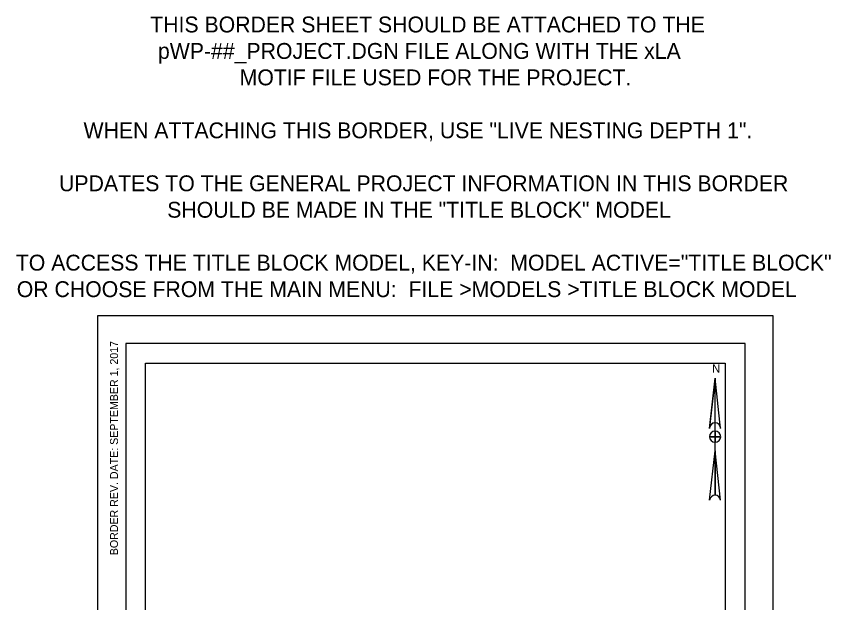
# Model space of a CAD drawing. Extents: x -1 to 9.2, y 0 to 14.8.
# Drawn here: x -1.03 to 9.23, y 7.38 to 14.77 of the extents above; entities that cross this region are included whole.
import ezdxf

# ---------------------------------------------------------------- set-up
doc = ezdxf.new("R2010")
doc.units = 0
for name, color, linetype in [('G-ANNO-SYMB', 7, 'Continuous'), ('G-BORD-LINE', 7, 'Continuous'), ('G-USER-CLIP', 7, 'Continuous'), ('G-USER-PAGE', 7, 'Continuous'), ('G-USER-TEXT', 7, 'Continuous')]:
    doc.layers.add(name, color=color, linetype=linetype)

msp = doc.modelspace()

# ---------------------------------------------------------------- linework, layer by layer
at = {"layer": 'G-ANNO-SYMB'}
for p, q in [((7.702, 9.58), (7.772, 10.213)), ((7.772, 8.738), (7.772, 10.213)), ((7.842, 9.58), (7.772, 10.213)), ((7.772, 9.475), (7.772, 9.546)), ((7.702, 9.475), (7.772, 9.475)), ((7.702, 9.475), (7.702, 9.475)), ((7.702, 9.475), (7.702, 9.475)), ((7.842, 9.475), (7.772, 9.475)), ((7.772, 9.475), (7.772, 9.405)), ((7.842, 9.475), (7.842, 9.475)), ((7.842, 9.475), (7.842, 9.475)), ((7.702, 8.676), (7.772, 9.299)), ((7.841, 8.676), (7.772, 9.299))]:
    msp.add_line(p, q, dxfattribs=at)
for points in [[(7.772, 9.65), (7.772, 9.65), (7.772, 10.213), (7.703, 9.596)], [(7.772, 9.546), (7.772, 9.475), (7.842, 9.475)], [(7.772, 9.405), (7.772, 9.475), (7.702, 9.475), (7.702, 9.475)], [(7.772, 9.405), (7.772, 9.405)], [(7.841, 8.676), (7.772, 9.299), (7.772, 8.738)]]:
    msp.add_lwpolyline(points, dxfattribs=at)
for centre, radius, start, end in [((7.772, 9.58), 0.0703, 90, 180), ((7.772, 9.58), 0.0703, 90.0905, 167.3484), ((7.772, 9.58), 0.0703, 0, 90), ((7.772, 9.475), 0.0703, 90, 180), ((7.772, 9.475), 0.0703, 0, 90), ((7.772, 9.475), 0.0703, 0.0012, 89.9988), ((7.772, 9.475), 0.0703, 180, 270), ((7.772, 9.475), 0.0703, 180, 270), ((7.772, 9.475), 0.0703, 270, 360), ((7.772, 8.668), 0.0698, 6.3439, 173.6561), ((7.772, 8.668), 0.0698, 6.3439, 90)]:
    msp.add_arc(centre, radius, start, end, dxfattribs=at)
at = {"layer": 'G-BORD-LINE'}
msp.add_lwpolyline([(0.35, 0.861), (0.35, 0.35), (8.15, 0.35), (8.15, 10.65), (0.35, 10.65), (0.35, 0.861)], dxfattribs=at)
at = {"layer": 'G-USER-CLIP'}
msp.add_lwpolyline([(0.6, 10.4), (7.9, 10.4), (7.9, 1.95), (0.6, 1.95)], close=True, dxfattribs=at)
at = {"layer": 'G-USER-PAGE'}
msp.add_lwpolyline([(0, 11), (8.5, 11), (8.5, 0), (0, 0)], close=True, dxfattribs=at)

# ---------------------------------------------------------------- texts
at = {"layer": 'G-ANNO-SYMB'}
msp.add_text('N', height=0.105, dxfattribs=at).set_placement((7.734, 10.283))
at = {"layer": 'G-USER-TEXT'}
for s, p in [('THIS BORDER SHEET SHOULD BE ATTACHED TO THE', (0.659, 14.566)), ('pWP-##_PROJECT.DGN FILE ALONG WITH THE xLA ', (0.756, 14.233)), ('MOTIF FILE USED FOR THE PROJECT.', (1.785, 13.9)), ('WHEN ATTACHING THIS BORDER, USE "LIVE NESTING DEPTH 1".', (-0.181, 13.233)), ('UPDATES TO THE GENERAL PROJECT INFORMATION IN THIS BORDER', (-0.489, 12.566)), ('SHOULD BE MADE IN THE "TITLE BLOCK" MODEL', (0.873, 12.233)), ('TO ACCESS THE TITLE BLOCK MODEL, KEY-IN:  MODEL ACTIVE="TITLE BLOCK"', (-1.034, 11.567)), ('OR CHOOSE FROM THE MAIN MENU:  FILE >MODELS >TITLE BLOCK MODEL', (-1.022, 11.233))]:
    msp.add_text(s, height=0.2, dxfattribs=at).set_placement(p)
msp.add_text('BORDER REV. DATE: SEPTEMBER 1, 2017', height=0.1, rotation=90, dxfattribs=at).set_placement((0.253, 7.983))

doc.saveas('drawing.dxf')
